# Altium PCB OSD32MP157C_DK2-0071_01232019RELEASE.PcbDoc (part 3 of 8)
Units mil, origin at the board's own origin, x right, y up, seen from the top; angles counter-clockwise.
Board outline 3976.38 x 2795.28 mil, 6 copper layers (Top Layer, Signal Layer 1, Signal Layer 2, Signal Layer 3, Signal Layer 4, Bottom Layer), stack 61.268 mil thick; 404 components, 418 nets, 1720 pads, 1233 vias.
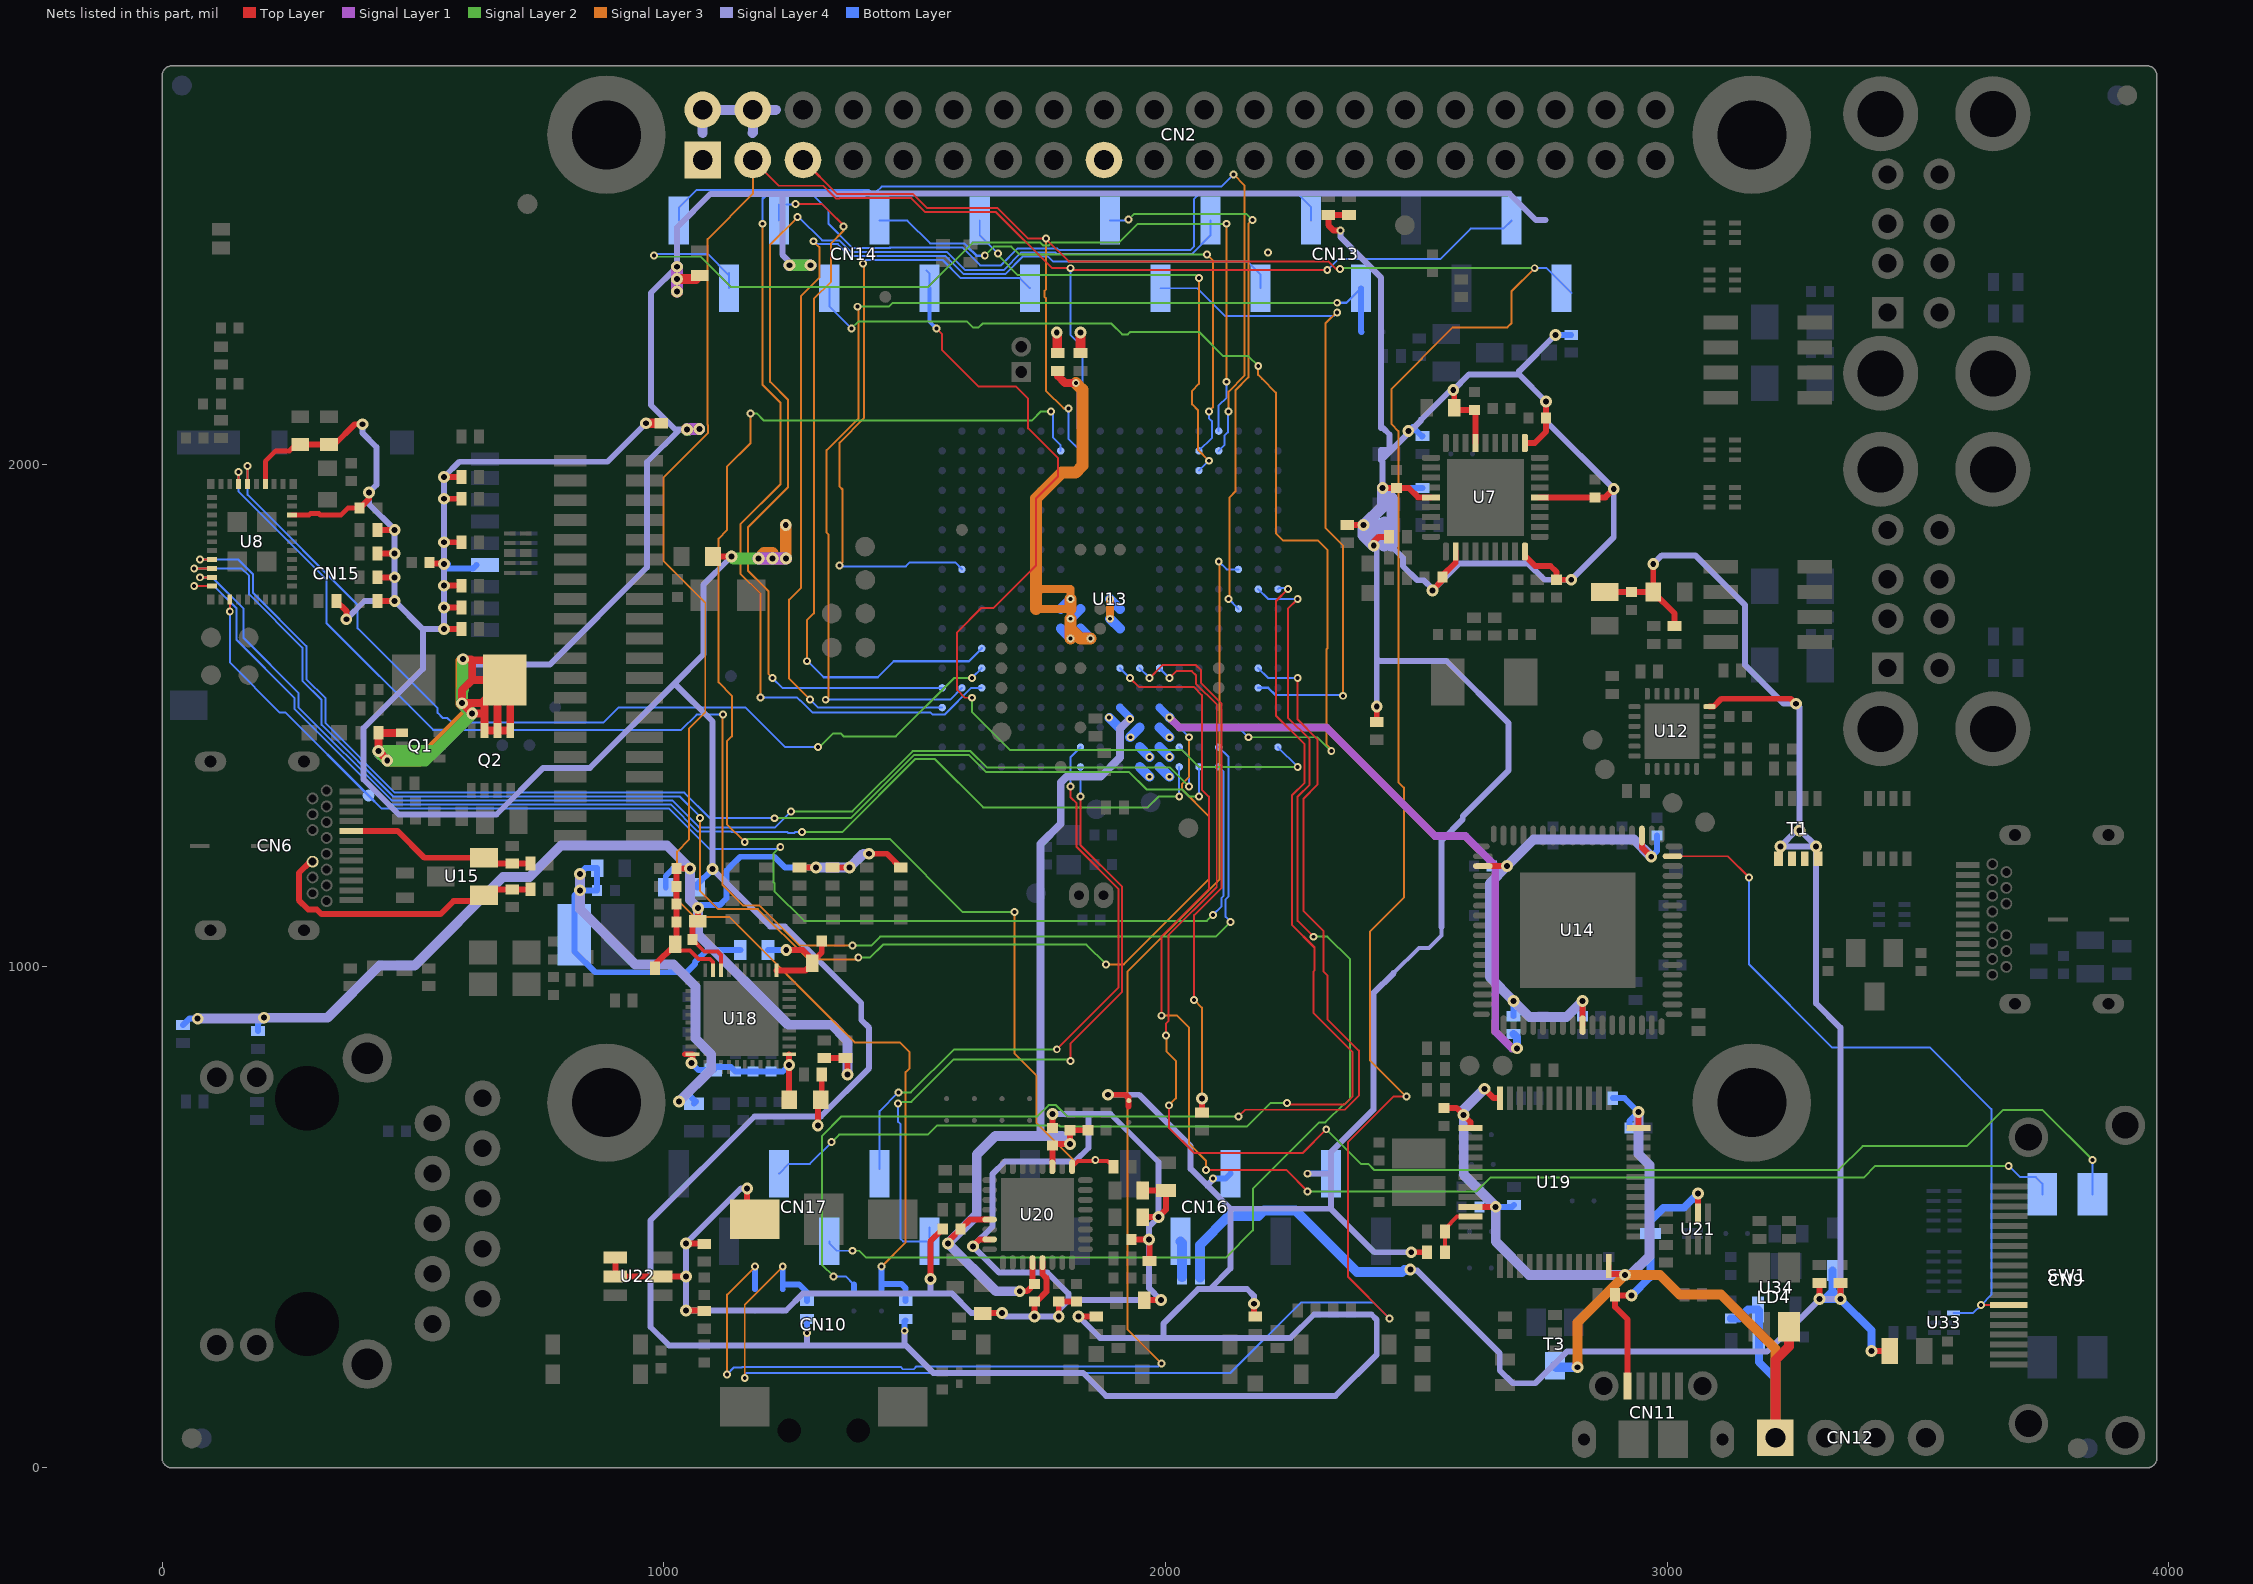
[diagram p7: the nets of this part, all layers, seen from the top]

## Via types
v1: diameter 15.75, hole 7.87, Top Layer to Bottom Layer, tented both sides, 803 vias
v2: diameter 23.62, hole 11.81, Top Layer to Bottom Layer, tented both sides, 417 vias
v3: diameter 15.75, hole 7.87, Top Layer to Bottom Layer, 13 vias

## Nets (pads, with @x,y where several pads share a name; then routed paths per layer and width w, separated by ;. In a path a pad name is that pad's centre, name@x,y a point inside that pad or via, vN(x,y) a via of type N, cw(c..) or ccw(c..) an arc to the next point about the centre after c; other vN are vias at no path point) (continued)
1V05_DVDD_GMII: C81.2 C85.2 R151.1 U18.21 | length 230.8
  Top Layer w11.81: U18.21@1224.41,992.13 1282.48,992.13 C85.2@1296.26,1005.91 C85.2@1296.26,1008.86 ; v2(1244.09,1032.48) 1277.56,1032.48 1296.26,1013.78 C85.2@1296.26,1008.86 ; C81.2@1314.96,1050.2 1314.96,1027.56 C85.2@1296.26,1008.86
  Bottom Layer w11.81: R151.1@1207.68,1032.48 v2(1244.09,1032.48)
1V05_GMII: C151.2 C157.2 LE1.2 R151.2 R160.2 | length 1332.6
  Signal Layer 4 w19.68: v2(832.68,1184.06) v2(832.68,1151.57) 832.68,1113.98 943.11,1003.54 1019.69,1003.54 1063.19,960.04 1063.19,855.91 1094.68,824.41 1094.68,794.54 v2(1030.44,730.31)
  Bottom Layer w11.81: v2(1030.44,730.31) 1047.21,747.08 1063.98,730.31 R160.2@1060.04,726.38 ; R151.2@1152.56,1032.48 1086.61,1032.48 1062.01,1007.87 1062.01,1004.47 1045.72,988.19 863.19,988.19 821.85,1029.53 LE1.2@821.85,1062.99 821.85,1140.75 v2(832.68,1151.57) ; v2(832.68,1151.57) C157.2@867.13,1151.57 C151.2@867.13,1195.87 843.5,1195.87 832.68,1185.04 v2(832.68,1184.06) v2(832.68,1151.57)
1V8_AUDIO: C94.2 C95.2 C97.2 C102.2 C107.2 U13.J4 U20.5 U20.12 U20.27 | length 1897.6
  Top Layer w3.54: v1(1929.13,1493.11) v1@1929.13,1494.59
  Top Layer w11.81: v2(1566.93,447.83) 1570.87,447.83 1570.87,455.71 C102.2@1591.54,476.38 1610.24,495.08 U20.5@1649.61,495.08 ; v2(1709.65,352.36) 1724.41,352.36 C107.2@1739.17,367.13 1735.24,371.06 U20.12@1735.24,409.45 ; U20.27@1774.61,600.39 C97.2@1774.61,642.72 1777.56,645.67 v2(1810.04,645.67) C94.2@1810.04,673.23 C95.2@1845.47,673.23
  Signal Layer 4 w15.75: 1749.02,662.01 1750.98,663.98 1750.98,1244.06 1791.34,1284.41 1791.34,1366.42 1802.87,1377.95 1870.97,1377.95 1909.45,1416.43 1909.45,1473.43 v1(1929.13,1493.11)
  Signal Layer 4 w19.68: v2(1709.65,352.36) 1662.4,352.36 v2(1566.93,447.83) 1624.02,504.92 1624.02,625.11 1660.91,662.01 1749.02,662.01 1793.7,662.01 v2(1810.04,645.67)
  Bottom Layer w3.54: U13.J4@1909.45,1514.27 U13.J4@1909.45,1515.75 ; v1(1929.13,1493.11) v1@1929.13,1494.59
  Bottom Layer w15.75: U13.J4@1909.45,1515.75 v1@1929.13,1496.06
3V3: C21.2 C23.2 C28.2 C29.2 C30.2 C38.2 C40.2 C45.2 C49.1 C50.2 C54.2 CN2.1 CN2.17 CN15.4 CN16.2 CN16.4 L7.1 L10.2 L11.2 R1.1 R2.1 R11.1 R14.2 R16.2 R17.1 R18.2 R19.2 R20.1 R22.1 R25.2 R26.1 R27.1 R28.2 R33.2 R40.1 R94.1 R105.2 R106.2 R114.2 R127.2 R134.2 R140.2 R166.1 R167.1 R300.1 R600.1 SB5.1 U7.5 U7.10 U7.15 U7.23 U7.29 U7.36 U8.30 U8.36 U13.H3 U13.J3 | length 15432.7
  Top Layer w9.84: U8.36@205.71,1961.61 205.71,2006.59 226.67,2027.56 253.94,2027.56 266.73,2040.35 C28.2@275.59,2040.35 ; U8.30@258.86,1899.61 292.62,1899.61 295.57,1902.56 312.7,1902.56 315.65,1899.61 356.3,1899.61 370.08,1913.39 C45.2@393.7,1913.39
  Top Layer w11.81: C28.2@275.59,2040.35 C29.2@332.68,2040.35 343.5,2040.35 383.85,2080.7 v2(399.61,2080.7) ; R26.1@347.45,1728.35 367.13,1708.67 v2(367.13,1691.93) ; C45.2@393.7,1913.39 412.4,1932.09 v2(412.4,1944.88) ; R27.1@429.14,1728.35 v2(463.59,1728.35) ; R22.1@429.14,1775.59 v2(463.59,1775.59) ; R20.1@429.14,1822.83 v2(463.59,1822.83) ; R17.1@429.14,1870.08 v2(463.59,1870.08) ; C49.1@533.07,1804.77 534.37,1803.47 560.71,1803.47 v2(562.01,1802.17) ; v2(562.01,1672.24) R33.2@596.46,1672.24 ; v2(562.01,1715.55) R28.2@596.46,1715.55 ; v2(562.01,1758.86) R25.2@596.46,1758.86 ; v2(562.01,1845.47) R19.2@596.46,1845.47 ; v2(562.01,1932.09) R16.2@596.46,1932.09 ; v2(562.01,1975.39) R14.2@596.46,1975.39 ; L7.1@1098.43,1816.93 v2(1134.84,1816.93) ; v2(1307.09,683.07) 1307.09,728.35 L10.2@1312.99,734.25 ; L10.2@1312.99,744.09 1314.96,746.06 R300.1@1314.96,784.45 ; v2(1826.77,302.17) R105.2@1862.2,302.17 ; v2(1885.83,744.09) 1920.28,744.09 1926.18,738.19 1926.18,720.47 ; v2(2176.38,327.36) 2176.38,304.92 R106.2@2179.13,302.17 ; v1(2349.41,2466.73) 2335.63,2466.73 2324.8,2477.56 R1.1@2324.8,2498.03 R2.1@2366.14,2498.03 ; R600.1@2362.45,1879.92 v2(2394.68,1879.92) ; v2(2415.35,1838.58) 2415.35,1846.46 2425.2,1856.3 R18.2@2445.87,1856.3 ; R40.1@2421.26,1487.2 v2(2421.26,1517.72) ; v2(2433.19,1953.84) 2460.53,1953.84 C38.2@2460.63,1953.74 2485.24,1953.74 2503.94,1935.04 U7.23@2529.53,1935.04 ; v2(2490.16,430.12) R94.1@2521.65,430.12 ; v2(2532.48,1749.02) 2532.48,1750 2552.17,1769.69 C50.2@2552.17,1776.57 2552.17,1778.54 2578.74,1805.12 U7.29@2578.74,1826.77 ; v2(2573.82,2148.62) 2575.79,2146.65 C23.2@2575.79,2113.19 2579.72,2109.25 C21.2@2616.14,2109.25 2618.11,2107.28 U7.15@2618.11,2043.31 ; U7.36@2716.54,1826.77 2716.54,1818.9 2737.2,1798.23 2767.72,1798.23 2779.53,1786.42 C54.2@2779.53,1770.67 v2(2809.06,1770.67) ; U7.10@2716.54,2043.31 2736.22,2043.31 2758.86,2065.94 C30.2@2758.86,2093.5 v2(2758.86,2125.98) ; U7.5@2746.06,1935.04 C40.2@2856.3,1935.04 2876.97,1935.04 v2(2893.7,1951.77)
  Top Layer w19.68: v2(964.57,2082.68) R11.1@995.08,2082.68
  Signal Layer 1 w23.62: v2(1188.98,1812.99) 1189.07,1813.08 v2(1243.99,1813.08)
  Signal Layer 2 w23.62: v2(1134.84,1816.93) 1138.69,1813.08 v2(1243.99,1813.08)
  Signal Layer 3 w23.62: v2(1243.11,1879.92) 1243.11,1813.97 v2(1243.99,1813.08) 1243.9,1812.99 v2(1216.54,1812.99) ; v2(1216.54,1812.99) 1216.54,1823.82 1199.8,1823.82 v2(1188.98,1812.99) v2(1216.54,1812.99)
  Signal Layer 4 w7.87: 2454.92,986.44 2505.48,1037.01 2525.59,1037.01 2550.39,1061.81 2550.39,1078.35
  Signal Layer 4 w11.81: v2(367.13,1691.93) 403.54,1728.35 v2(463.59,1728.35) ; v2(399.61,2080.7) 399.61,2062.99 427.17,2035.43 427.17,1959.65 v2(412.4,1944.88) 412.4,1921.27 v2(463.59,1870.08) v2(463.59,1822.83) v2(463.59,1775.59) v2(463.59,1728.35) ; v2(964.57,2082.68) 887.8,2005.91 592.52,2005.91 v2(562.01,1975.39) v2(562.01,1932.09) v2(562.01,1845.47) v2(562.01,1802.17) v2(562.01,1758.86) v2(562.01,1715.55) v2(562.01,1672.24) 519.69,1672.24 ; v2(1134.84,1816.93) v2@1131,1813.08 ; v2(1243.99,1813.08) v2@1131,1813.08 ; v1(1285.43,268.7) 1285.43,244.09 ; v1(1480.31,273.62) 1480.31,246.46 1482.29,244.49 ; v2(1826.77,302.17) 1869.49,259.45 1967.72,259.45 1995.28,259.45 ; v2(1885.83,744.09) 1947.64,744.09 2050.39,641.34 2050.39,596.26 2084.15,562.5 ; v3(2094.49,576.77) 2094.49,574.8 2084.15,564.47 2084.15,562.5 ; v2(2176.38,327.36) 2176.38,343.31 2162.8,356.89 2088.98,356.89 ; v3(2283.46,586.61) 2329.92,586.61 ; v1(2349.41,2466.73) 2349.41,2453.74 2430.12,2373.03 2430.12,2072.83 2434.17,2072.83 2446.85,2060.15 2446.85,2033.46 2442.91,2029.53 2430.12,2029.53 2430.12,2008.86 ; v2(2421.26,1517.72) 2421.26,1613.78 ; v2(2433.19,1953.84) 2433.19,2005.79 2430.12,2008.86 ; 2454.92,986.44 2414.57,946.09 2414.57,714.17 2329.92,629.53 2329.92,586.61 ; v2(2490.16,430.12) 2416.54,430.12 2329.92,516.73 ; v2(2532.48,1749.02) v2@2532.48,1750 ; 2550.39,1078.35 2550.39,1250.59 2592.8,1293 2592.8,1299.35 2684.25,1390.8 2684.25,1484.84 2560.24,1608.86 2426.18,1608.86 2421.26,1613.78 ; v2(2777.56,2258.86) 2705.12,2186.42 2705.12,2179.72 ; v2(463.59,1728.35) 519.69,1672.24 ; 519.69,1672.24 519.69,1592.92 401.57,1474.8 401.57,1372.83 471.65,1302.76 666.54,1302.76 759.45,1395.67 852.95,1395.67 1020.87,1563.58 ; 1020.87,1563.58 1021.85,1563.58 1097.44,1487.99 v2(1097.44,1193.9) 1212.01,1079.33 1241.34,1079.33 1393.7,926.97 1393.7,893.17 1409.45,877.42 1409.45,797.13 1313.1,700.79 1307.09,700.79 1180.71,700.79 973.62,493.7 973.62,281.1 1010.63,244.09 1285.43,244.09 ; 1020.87,1563.58 1078.94,1621.65 1078.94,1761.02 v2@1131,1813.08 ; 1285.43,244.09 1482.29,244.09 1482.29,244.49 ; 1482.29,244.49 1537.21,189.57 1835.83,189.57 1881.69,143.7 2339.17,143.7 2421.26,225.79 2421.26,295.72 2410.88,306.1 2296.15,306.1 2249.5,259.45 1995.28,259.45 ; 1995.28,259.45 1995.96,260.14 1995.96,287.7 2065.16,356.89 2088.98,356.89 ; 2084.15,562.5 2129.92,516.73 ; 2088.98,356.89 2129.92,397.83 2129.92,516.73 ; 2129.92,516.73 2329.92,516.73 ; 2329.92,516.73 2329.92,586.61 ; 2421.26,1613.78 2421.26,1832.68 v2(2415.35,1838.58) 2436.02,1838.58 2449.61,1838.58 2473.62,1814.57 2473.62,1797.83 2501.78,1769.68 2515.21,1769.68 2532.48,1752.41 v2@2532.48,1750 ; 2430.12,2008.86 2484.25,2062.99 v2(2484.25,2066.92) 2484.25,2070.85 2488.18,2066.92 2509.84,2088.58 2509.84,2090.02 2568.45,2148.62 v2(2573.82,2148.62) 2604.92,2179.72 2705.12,2179.72 ; v2@2532.48,1750 2585.23,1802.76 2723.62,1802.76 2755.71,1770.67 v2(2809.06,1770.67) 2893.7,1855.31 v2(2893.7,1951.77) 2893.59,1951.77 2758.86,2086.5 v2(2758.86,2125.98) 2705.12,2179.72
  Signal Layer 4 w23.62: v2@2395.67,1877.95 2411.42,1862.2 2412.4,1862.2 ; v2(2415.35,1838.58) 2394.68,1859.25 v2(2394.68,1879.92) v2@2395.67,1878.94 ; v2(2433.19,1953.84) v2@2433.19,1950.67 ; 2436.02,1838.58 2412.4,1862.2 ; 2449.61,1838.58 2452.76,1841.73 2452.76,1931.1 v2@2433.19,1950.67 ; v2@2395.67,1878.94 2433.19,1916.46 v2@2433.19,1950.67 ; v2@2395.67,1878.94 2412.4,1862.2 ; v2@2395.67,1878.94 2431.1,1878.94 2437.01,1884.84 2437.01,1862.2 2412.4,1862.2
  Bottom Layer w11.81: v2(562.01,1802.17) v2@569.88,1802.17 ; v2@565.45,1797.74 561.02,1793.31 620.08,1793.31 CN15.4@626.97,1800.2 ; L11.2@1066.93,1157.48 1066.93,1163.39 v2(1097.44,1193.9) ; v1(1285.43,268.7) R167.1@1285.43,297.24 ; v1(1480.31,273.62) 1480.31,292.52 R166.1@1482.29,294.49 ; v1(1887.8,1496.06) v1@1888.55,1495.31 ; v3(2094.49,576.77) 2119.9,576.77 CN16.4@2129.92,586.79 ; v3(2283.46,586.61) 2283.64,586.79 CN16.2@2329.92,586.79 ; v2(2394.68,1879.92) R140.2@2423.23,1879.92 ; v2(2433.19,1953.84) 2430.21,1953.84 2430.12,1953.74 R134.2@2512.8,1953.74 ; v2(2484.25,2066.92) 2484.25,2067.9 2485.23,2066.92 2493.11,2074.8 2511.81,2056.1 R127.2@2512.8,2057.09 ; v2(2777.56,2258.86) R114.2@2809.06,2258.86
  Bottom Layer w19.68: v1@1888.55,1495.31 1907.48,1476.38 U13.J3@1909.45,1476.38 ; v1@1929.13,1456.69 U13.H3@1948.82,1476.38
  Bottom Layer w23.62: v2(1188.98,1812.99) v2(1216.54,1812.99) 1243.9,1812.99 v2(1243.99,1813.08)
  other v1: 1930.13,1456.69
3V3_AVDD_GMII: C173.2 C174.2 C175.2 C176.2 L10.1 U18.11 U18.40 | length 326.2
  Top Layer w11.81: 1042.32,824.8 U18.40@1057.09,824.8 1057.09,809.04 v2(1055.17,807.13) ; L10.1@1250,744.09 v2(1250,803.15) U18.11@1250,824.8
  Bottom Layer w11.81: v2(1055.17,807.13) 1068.99,793.31 C173.2@1098.43,793.31 1098.72,793.01 1104.92,799.21 1133.86,799.21 C176.2@1142.72,790.35 C175.2@1178.15,790.35 C174.2@1213.58,790.35 1237.2,790.35 v2(1250,803.15)
3V3_DVDD_GMII: C74.2 C75.2 C76.1 C77.2 C78.2 C79.2 C80.2 L11.1 R52.2 R53.2 R55.2 R65.2 R75.2 R76.2 R156.1 R157.2 U18.28 U18.29 | length 3058.1
  Top Layer w7.87: C80.2@1022.64,1044.29 1022.64,1043.31 1022.64,1034.45 1025.59,1031.5 1052.17,1031.5 1068.9,1014.76 1092.52,1014.76 1098.43,1008.86 U18.29@1098.43,992.13 ; C79.2@1055.12,1051.18 C79.2@1057.09,1053.15 1080.71,1029.53 1107.28,1029.53 1114.17,1022.64 U18.28@1114.17,992.13
  Top Layer w11.81: R65.2@982.28,996.06 982.28,1002.95 C80.2@1022.64,1043.31 ; C80.2@1022.64,1044.29 1025.59,1047.24 C78.2@1025.59,1088.58 C77.2@1025.59,1124.02 C75.2@1025.59,1159.45 C74.2@1025.59,1194.88 v2(1052.17,1194.88) ; C79.2@1057.09,1053.15 1057.09,1078.74 C76.1@1067.91,1089.57 1067.91,1116.13 v2(1067.97,1116.19) ; R52.2@1270.67,1196.85 v2(1303.15,1196.85) ; R75.2@1319.88,816.93 R76.2@1362.2,816.93 1361.42,816.14 1366.14,811.42 v2(1366.14,784.45) ; R53.2@1337.6,1196.85 v2(1370.08,1196.85) ; v2(1409.45,1224.41) 1444.88,1224.41 R55.2@1472.44,1196.85
  Signal Layer 4 w19.68: v2(70.87,895.67) 200.79,895.67 v2(202.76,897.64) 329.33,897.64 433.27,1001.57 503.54,1001.57 679.72,1177.76 732.48,1177.76 795.47,1240.75 1006.3,1240.75 v2(1052.17,1194.88) 1052.17,1131.99 v2(1067.97,1116.19) 1067.97,1063.72 1248.23,883.46 1335.04,883.46 1350.39,868.11 1350.39,867.01 1363.08,854.33 1364.17,854.33 1366.14,852.36 v2(1366.14,784.45) ; v2(1303.15,1196.85) v2(1370.08,1196.85) 1397.64,1224.41 v2(1409.45,1224.41)
  Bottom Layer w11.81: R156.1@41.34,882.87 54.13,895.67 v2(70.87,895.67) ; R157.2@190.94,871.06 190.94,885.83 v2(202.76,897.64) ; L11.1@1003.94,1157.48 1003.94,1180.12 1018.7,1194.88 v2(1052.17,1194.88) ; v2(1067.97,1116.19) 1074.31,1122.54 1074.8,1122.05 1111.33,1122.05 1125,1135.72 1125,1190.83 1133.86,1199.69 1133.86,1200.2 1152.17,1218.5 1220.47,1218.5 1242.13,1196.85 v2(1303.15,1196.85)
3V3_HDMI: R154.2 U13.G4 | length 1218.8
  Signal Layer 1 w15.75: v1(2007.87,1496.06) 2027.56,1476.38 2320.87,1476.38 2537.78,1259.46 2598.43,1259.46 2657.48,1200.41 2657.48,870.08 2690.94,836.61 v2(2700.79,836.61)
  Bottom Layer w15.75: U13.G4@1988.19,1515.75 v1(2007.87,1496.06) ; R154.2@2693.9,865.16 2700.79,858.27 v2(2700.79,836.61)
3V3_IOVCC: C140.2 C154.2 C171.2 R154.1 U14.3 U14.21 U14.46 | length 1075.2
  Top Layer w11.81: U14.21@2632.87,1199.8 v2(2681.1,1199.8) ; U14.46@2831.69,882.87 v2(2831.69,931.1) ; U14.3@2949.8,1260.83 2949.8,1237.2 v2(2968.5,1218.5)
  Signal Layer 4 w19.68: v2(2831.69,931.1) 2799.8,899.21 2725.79,899.21 v2(2693.9,931.1) 2646.85,978.15 2646.85,1165.55 v2(2681.1,1199.8) 2733.86,1252.56 2934.45,1252.56 v2(2968.5,1218.5)
  Bottom Layer w11.81: C154.2@2650.59,1199.8 v2(2681.1,1199.8) ; R154.1@2693.9,900.59 v2(2693.9,931.1) ; C171.2@2831.69,900.59 v2(2831.69,931.1) ; v2(2968.5,1218.5) 2980.31,1230.31 C140.2@2980.31,1260.83
3V3_ST_LINK: C93.2 C181.2 C184.2 C186.2 C188.2 C190.2 CN12.1 LD4.4 R158.2 R161.2 T3.3 U19.1 U19.9 U19.24 U19.36 U19.48 U34.5 | length 2827.8
  Top Layer w11.81: C93.2@2555.12,717.52 2580.51,717.52 v2(2594.39,703.64) 2608.27,689.76 U19.1@2608.27,678.15 ; U19.9@2608.27,520.67 v2(2658.46,520.67) ; v2(2635.83,755.91) 2654.53,737.2 U19.48@2667.32,737.2 ; U19.24@2883.86,402.56 2883.86,386.81 2914.37,386.81 v2(2916.34,384.84) ; U19.36@2942.91,678.15 v2(2942.91,709.65)
  Top Layer w19.68: CN12.1@3216.14,60.04 3216.14,215.16 3243.11,242.13 LD4.4@3243.11,281.5
  Signal Layer 3 w19.68: v2(2821.85,200.79) 2821.85,290.35 v2(2916.34,384.84) 2986.02,384.84 3024.8,346.06 3107.48,346.06 3216.14,237.4 CN12.1@3216.14,60.04
  Signal Layer 4 w19.68: v2(2594.39,703.64) 2594.39,714.47 v2@2594.68,714.76 ; v2(2635.83,755.91) v2@2594.68,714.76 ; v2(2942.91,709.65) 2942.91,625.79 2964.76,603.94 2964.76,422.83 2926.77,384.84 v2(2916.34,384.84) 2725,384.84 2658.46,451.38 v2(2658.46,520.67) 2594.68,584.45 v2@2594.68,714.76
  Bottom Layer w11.81: C184.2@2625.98,520.67 v2(2658.46,520.67) 2690.94,520.67 R161.2@2694.88,524.61 ; C186.2@2883.86,384.84 v2(2916.34,384.84) ; R158.2@2891.73,737.2 2915.35,737.2 v2(2942.91,709.65) 2925.2,691.93 C181.2@2925.2,678.15
  Bottom Layer w15.75: C188.2@3126.97,298.23 3143.7,298.23 3161.42,315.94 U34.5@3181.1,315.94 3183.07,313.98 C190.2@3183.07,251.97 3183.07,211.22 3216.14,178.15 CN12.1@3216.14,60.04
  Bottom Layer w19.68: T3.3@2776.57,203.74 2779.53,200.79 v2(2821.85,200.79)
5V: CN16.5 R165.2 | length 73.3
  Bottom Layer w11.81: R165.2@2033.07,380.31 R165.2@2033.46,379.92
  Bottom Layer w19.68: CN16.5@2029.92,451.79 2033.07,448.64 R165.2@2033.07,380.31
5V_USB_ST_LINK: CN11.1 D2.1 R99.1 U21.5 | length 547.2
  Top Layer w11.81: CN11.1@2921.26,163.39 2921.26,296.26 2896.65,320.87 R99.1@2896.65,345.47 2898.62,343.5 v2(2929.13,343.5) ; U21.5@3062.01,508.07 v2(3062.01,547.24)
  Bottom Layer w15.75: v2(2929.13,343.5) 2966.73,381.1 D2.1@2966.73,467.52 2966.73,492.32 2993.11,518.7 3033.46,518.7 v2(3062.01,547.24)
5V_VIN: C55.2 C56.2 C60.1 CN2.2 CN2.4 D1.1 F1.1 L8.1 Q1.4 Q2.1 Q2.2 Q2.3 R9.1 R12.2 R32.2 R41.2 R97.2 R98.2 R165.1 T1.5 T1.6 T1.7 T1.8 U12.24 U13.G1 U13.G2 U13.G3 U13.H1 U13.H2 U23.1 | length 10501.4
  Top Layer w11.81: C55.2@2875.98,1746.06 C56.2@2929.13,1746.06 L8.1@2972.44,1746.06 ; v2(2972.44,1802.17) L8.1@2972.44,1746.06 ; R32.2@3014.76,1678.15 3014.76,1703.74 L8.1@2972.44,1746.06 ; U12.24@3084.65,1517.72 3092.52,1517.72 3108.27,1533.46 3246.85,1533.46 v2(3256.89,1523.43) ; v2(3304.13,336.61) R97.2@3304.13,369.09 ; v2(3345.47,336.61) R98.2@3345.47,369.09 ; v2(3407.48,233.27) F1.1@3441.93,233.27 ; F1.1@3443.9,235.24 F1.1@3441.93,233.27 ; F1.1@3444.88,234.25 F1.1@3443.9,233.27 F1.1@3441.93,233.27
  Top Layer w15.75: v2(448.82,1410.43) 448.82,1411.42 v2(431.1,1429.13) R41.2@431.1,1465.55 Q1.4@478.35,1465.55 ; v2(599.44,1612.28) 615.08,1612.28 ; v2(618.11,1503.94) 642.72,1503.94 ; v2@618.14,1503.97 v2(597.44,1524.61) ; 618.14,1570.84 597.44,1550.14 v2(597.44,1524.61) v2(597.44,1524.61) ; v2(1783.46,2263.78) v2@1784.45,2262.8 ; R12.2@1784.45,2223.43 R12.2@1785.43,2222.44 ; v2(597.44,1524.61) 636.81,1524.61 C60.1@642.72,1530.51 ; 615.08,1612.28 616.06,1612.28 618.11,1610.24 ; 615.08,1612.28 617.13,1610.24 618.11,1610.24 ; 618.11,1610.24 683.07,1610.24 C60.1@683.07,1570.87 ; 618.11,1610.24 618.11,1570.87 C60.1@683.07,1570.87 ; 642.72,1503.94 C60.1@642.72,1530.51 ; 642.72,1503.94 Q2.3@642.72,1470.47 Q2.2@668.31,1470.47 ; C60.1@642.72,1530.51 C60.1@668.31,1556.1 ; Q2.2@668.31,1470.47 Q2.1@693.9,1470.47 693.9,1560.04 C60.1@683.07,1570.87 ; Q2.2@668.31,1470.47 C60.1@668.31,1556.1 ; C60.1@668.31,1556.1 C60.1@683.07,1570.87
  Top Layer w19.68: v2(1026.57,2370.08) 1064.57,2370.08 U23.1@1071.85,2377.36 ; R12.2@1784.45,2223.43 v2@1784.45,2262.8 ; R9.1@1830.71,2222.44 v2(1830.71,2263.78)
  Signal Layer 1 w23.62: v2(1026.57,2345.47) v2(1026.57,2370.08) v2(1026.57,2394.69) ; v2@1047.24,2070.87 v2(1070.87,2070.87)
  Signal Layer 2 w11.81: v2(1046.26,2069.98) 1047.29,2069.98 1053.35,2069.98 1054.24,2070.87 v2@1055.17,2071.8
  Signal Layer 2 w23.62: v2(599.44,1612.28) 599.44,1552.14 597.44,1550.14 v2(597.44,1524.61) v2(597.44,1524.61) v2@618.14,1503.97 ; v2(618.11,1503.94) 543.31,1429.13 ; v2(1026.57,2345.47) v2(1026.57,2370.08) v2(1026.57,2394.69) ; v2(1046.26,2069.98) 1047.34,2068.9 1047.31,2069.66 1047.29,2069.98 1047.29,2070.04 1047.24,2070.87 1054.24,2070.87 v2(1070.87,2070.87) ; v2(1250.98,2397.64) v2(1292.32,2397.64) ; 543.31,1429.13 v2(431.1,1429.13) 431.1,1428.15 v2(448.82,1410.43) 524.61,1410.43 543.31,1429.13
  Signal Layer 3 w23.62: v2(599.44,1612.28) 596.46,1609.3 596.46,1523.62 v2(597.44,1524.61) v2(597.44,1524.61) v2@618.14,1503.97 ; v2(618.11,1503.94) 607.28,1503.94 532.48,1429.13 ; v2(1026.57,2345.47) v2(1026.57,2370.08) v2(1026.57,2394.69) ; v2(1046.26,2069.98) 1047.34,2068.9 1047.31,2069.66 1047.29,2070.04 1047.24,2070.87 v2(1070.87,2070.87) ; 532.48,1429.13 v2(431.1,1429.13) 431.1,1428.15 v2(448.82,1410.43) 513.78,1410.43 532.48,1429.13
  Signal Layer 4 w11.81: v2(597.44,1524.61) v2(597.44,1524.61) v2@599.44,1522.61 ; v2(599.44,1612.28) 610.34,1601.38 772.64,1601.38 966.73,1795.47 966.73,2005.51 1031.2,2069.98 ; v2@618.11,1501.97 v2(618.11,1503.94) ; v2@1055.17,2069.98 v2(1046.26,2069.98) 1031.2,2069.98 ; 1236.42,2536.02 1236.42,2418.9 1257.68,2397.64 v2(1292.32,2397.64) v2@1289.37,2394.69 ; v2(2488.19,395.67) 2490.45,393.41 2502.06,393.41 2666.54,228.94 2666.54,194.49 2692.13,168.9 2737.4,168.9 2800.39,231.89 3199.41,231.89 v2(3304.13,336.61) v2(3345.47,336.61) 3345.47,877.76 3297.24,925.98 v2(3297.24,1239.17) ; 2757.87,2487.8 2738.58,2487.8 2686.02,2540.35 1400.65,2540.35 1400.05,2539.76 1092.91,2539.76 1026.57,2473.43 v2(1026.57,2394.69) 974.61,2342.72 974.61,2118.7 1023.32,2069.98 1031.2,2069.98 ; v2(2972.44,1802.17) 2989.67,1819.4 3056.39,1819.4 3155.71,1720.08 3155.71,1600.2 3232.48,1523.43 v2(3256.89,1523.43) 3263.78,1516.54 v2(3263.78,1270.67) ; v2(3263.78,1270.67) 3257.87,1270.67 v2(3226.38,1239.17) v2(3297.24,1239.17) ; v2(3263.78,1270.67) 3265.75,1270.67 v2(3297.24,1239.17)
  Signal Layer 4 w19.68: v2(431.1,1429.13) 440.95,1419.29 535.43,1419.29 v2@618.11,1501.97 ; v2(597.44,1524.61) v2@599.44,1522.67 ; v2@599.44,1522.61 v2@599.44,1522.67 ; v2(599.44,1612.28) v2@599.44,1522.67 ; v2@618.14,1503.97 v2@599.44,1522.67 ; 1077.76,2661.61 1077.56,2661.81 CN2.2@1077.56,2707.48 CN2.4@1177.56,2707.48 ; 1177.17,2661.61 1177.56,2662.01 CN2.4@1177.56,2707.48 ; 1223.43,2707.68 1223.23,2707.48 CN2.4@1177.56,2707.48
  Bottom Layer w15.75: v2(3304.13,336.61) v2@3313.98,336.61 ; D1.1@3329.72,393.9 3329.72,352.36 ; v2(3407.48,233.27) 3407.48,274.61 v2(3345.47,336.61) ; v2@3313.98,336.61 v2(3345.47,336.61) ; v2@3313.98,336.61 3329.72,352.36 ; 3329.72,352.36 v2(3345.47,336.61)
  Bottom Layer w19.68: U13.H1@1948.82,1397.64 v1(1968.5,1377.95) ; U13.H2@1948.82,1437.01 v1(1968.5,1417.32) ; U13.G1@1988.19,1397.64 v1(2007.87,1377.95) ; U13.G2@1988.19,1437.01 v1(2007.87,1417.32) ; U13.G3@1988.19,1476.38 v1(2007.87,1456.69) ; R165.1@2068.9,379.92 2068.9,444.88 2125.98,501.97 2185.26,501.97 2196.36,513.07 2259.12,513.07 2381.68,390.51 2471.87,390.51 2476.28,394.92 2487.44,394.92 v2(2488.19,395.67)
  Bottom Layer w23.62: v2(431.1,1429.13) 431.1,1428.15 v2(448.82,1410.43) ; v2(597.44,1524.61) v2(597.44,1524.61) v2@618.14,1503.97 ; v2(1026.57,2345.47) v2(1026.57,2370.08) v2(1026.57,2394.69) ; v2(1046.26,2069.98) 1047.34,2068.9 1047.31,2069.66 1047.29,2070.04 1047.24,2070.87 v2(1070.87,2070.87) ; v2(1250.98,2397.64) v2(1292.32,2397.64)
  other v1: 2204.72,2423.23
AGND: C97.1 C100.1 C101.1 C102.1 C103.1 C107.1 C108.1 C109.1 C110.1 C111.1 CN10.2 R83.1 R92.1 R96.1 R103.1 U20.7 U20.13 U22.2 U22.4 U22.5 | length 3532.5
  Top Layer w11.81: U22.4@903.54,419.29 U22.5@903.54,381.89 U22.2@994.09,381.89 v2(1044.29,381.89) ; v2(1044.29,313.98) 1079.72,313.98 R103.1@1080.71,312.99 ; v2(1044.29,447.83) 1079.72,447.83 R92.1@1080.71,446.85 ; v2(1166.34,557.09) 1166.34,510.83 CN10.2@1181.1,496.06 ; v2(1531.5,376.57) 1531.5,451.77 C102.1@1556.1,476.38 ; v2(1616.14,441.93) 1629.92,455.71 U20.7@1649.61,455.71 ; C110.1@1635.83,308.07 1636.81,309.06 v2(1674.21,309.06) ; v2(1739.17,302.17) C107.1@1739.17,331.69 1743.11,331.69 1762.8,351.38 1762.8,378.49 1754.92,386.36 U20.13@1754.92,409.45 ; C97.1@1774.61,678.15 v2(1774.61,705.71) ; v2(1787.4,302.17) C108.1@1787.4,331.69 C109.1@1822.83,331.69 ; C103.1@1932.09,455.71 v2(1967.52,455.71) 1968.5,454.72 R96.1@1968.5,412.4 ; C101.1@1954.72,500 1987.2,500 v2(1986.22,500) 2000.98,514.76 R83.1@2000.98,553.15 C100.1@1954.72,553.15 ; C111.1@1957.68,334.65 v2(1991.14,334.65)
  Signal Layer 4 w11.81: v2(1166.34,557.09) 1153.54,557.09 v2(1044.29,447.83) v2(1044.29,381.89) v2(1044.29,313.98) 1243.7,313.98 1277.76,348.03 1531.69,348.03 ; v2(1531.5,376.57) 1531.69,376.38 1531.69,348.03 ; v2(1774.61,705.71) 1847.64,705.71 ; 1531.69,348.03 1574.02,348.03 1612.99,309.06 v2(1674.21,309.06) 1681.1,302.17 v2(1739.17,302.17) v2(1787.4,302.17) 1787.4,315.35 1806.69,334.65 ; 1806.69,334.65 1806.69,347.64 1764.96,389.37 1668.7,389.37 v2(1616.14,441.93) 1655.71,481.5 1655.71,586.22 1680.31,610.83 1819.49,610.83 1846.65,637.99 1846.65,704.72 1847.64,705.71 ; 1806.69,334.65 v2(1991.14,334.65) 1967.52,358.27 v2(1967.52,455.71) 1967.52,481.3 v2(1986.22,500) 1986.22,610.04 1890.55,705.71 1847.64,705.71
AIN_1: R91.2 R94.2 U19.10 | length 107.6
  Top Layer w7.87: R94.2@2557.09,430.12 R91.2@2557.09,471.46 2557.09,476.38 2581.69,500.98 U19.10@2608.27,500.98
ARD_A0: CN17.1 U13.L1 | length 1405
  Top Layer w3.94: v1(1811.02,811.02) 1811.02,846.46 1913.78,949.21 1913.78,1158.32 1830.71,1241.39 v1(1830.71,1338.58)
  Signal Layer 2 w3.94: v1(1466.73,726.97) 1469.67,729.91 1493.69,729.91 1578.34,814.56 1807.49,814.56 v1(1811.02,811.02)
  Bottom Layer w3.94: v1(1466.73,726.97) 1466.73,690.75 1471.65,685.83 1471.65,489.76 1471.65,457.28 1477.15,451.79 CN17.1@1529.92,451.79 CN17.1@1529.92,478.94 ; v1(1830.71,1338.58) U13.L1@1830.71,1397.64
ARD_A1: CN17.2 U13.L2 | length 1220.3
  Top Layer w3.94: v1(1783.46,834.65) 1906.3,957.48 1906.3,1154.5 1822.83,1237.96 1822.83,1324.8 1811.02,1336.61 v1(1811.02,1358.27)
  Signal Layer 2 w3.94: v1(1467.7,748.61) 1492.72,748.62 1578.74,834.65 v1(1783.46,834.65)
  Bottom Layer w3.94: CN17.2@1430.31,596.06 1430.31,711.22 v1(1467.7,748.61) ; v1(1811.02,1358.27) 1811.02,1417.32 U13.L2@1830.71,1437.01
ARD_A2: CN17.3 U13.B10 | length 2412.8
  Top Layer w3.94: v1(2263.78,1732.28) 2244.09,1712.6 2244.09,1495.67 2287.4,1452.36 2287.4,1362.2 2263.78,1338.58 2263.78,1090.55 v1(2295.28,1059.06)
  Signal Layer 2 w3.94: v1(1375.98,433.07) 1389.76,433.07 1403.54,419.29 2120.08,419.29 2174.41,473.62 2174.41,556.3 2307.09,688.98 2318.9,688.98 2355.31,725.39 2357.73,725.39 2368.11,735.77 2368.11,1013.78 2322.83,1059.06 v1(2295.28,1059.06)
  Bottom Layer w3.94: CN17.3@1330.33,451.38 CN17.3@1329.92,451.79 1329.92,447.64 1344.49,433.07 v1(1375.98,433.07) ; U13.B10@2185.04,1751.97 2204.72,1732.28 v1(2263.78,1732.28)
ARD_A3: CN17.4 U13.A10 | length 2338.6
  Top Layer w3.94: v1(2242.32,727.95) 2245.32,724.95 2357.29,724.95 2373.03,740.69 2373.03,828.74 2295.28,906.5 2295.28,990.16 2297.24,992.13 2297.24,1037.6 2251.97,1082.88 2251.97,1340.55 2277.56,1366.14 2277.56,1442.72 2220.47,1499.8 2220.47,1728.35 v1(2244.09,1751.97)
  Signal Layer 2 w3.94: v1(1334.65,649.61) 1349.41,664.37 1526.57,664.37 1545.28,683.07 1788.08,683.07 1790.05,681.1 2162.83,681.1 2209.68,727.95 v1(2242.32,727.95)
  Bottom Layer w3.94: CN17.4@1229.92,586.79 1249.43,606.3 1291.34,606.3 v1(1334.65,649.61) ; U13.A10@2224.41,1751.97 2226.58,1754.13 v1@2244.09,1754.13
ARD_A4: SB24.1 U13.B6 | length 2461.7
  Top Layer w3.94: v1(2145.67,700.79) 2159.04,714.16 2357.63,714.16 2385.83,742.35 2385.83,831.89 2322.83,894.88 2322.83,982.09 2314.96,989.96 2314.96,1070.87 2275.59,1110.24 2275.59,1334.65 2303.15,1362.2 2303.15,1452.76 2263.78,1492.13 v1(2263.78,1574.8)
  Signal Layer 2 w3.94: v1(1338.58,381.89) 1314.96,405.51 1314.96,661.42 1354.33,700.79 1744.63,700.79 1767.27,723.43 1781.94,723.43 1804.58,700.79 v1(2145.67,700.79)
  Bottom Layer w3.94: v1(1338.58,381.89) 1362.8,381.89 1378.94,365.75 ; U13.B6@2185.04,1594.49 2204.72,1574.8 v1(2263.78,1574.8)
  Bottom Layer w11.81: SB24.1@1378.94,356.3 1378.94,365.75
ARD_A5: SB26.1 U13.C11 | length 2912
  Signal Layer 3 w3.94: v1(1126.18,186.61) 1126.18,345.67 v1(1182.09,401.57) ; v1(1992.13,208.66) 1924.21,276.57 1924.21,989.67 2108.26,1173.72 2108.26,1745.47 2108.27,1805.12 v1(2106.3,1807.09)
  Bottom Layer w3.94: v1(1126.18,186.61) 1139.96,200.39 1155.91,200.39 1156.89,201.38 1472.05,201.38 1476.58,196.85 1497.91,196.85 1503.82,202.76 1576.01,202.76 1576.41,202.36 1985.83,202.36 v1(1992.13,208.66) ; v1(2106.3,1807.09) 2122.05,1791.34 U13.C11@2145.67,1791.34
  Bottom Layer w11.81: SB26.1@1182.09,356.3 v1(1182.09,401.57)
ARD_D0: CN14.1 U13.D17 | length 1743.6
  Signal Layer 3 w3.94: v1(2125.98,2106.3) 2125.98,2145.87 2157.48,2177.36 2157.48,2557.08 v1(2135.82,2578.73)
  Bottom Layer w3.94: CN14.1@1029.92,2486.79 1029.92,2512.6 1065.39,2548.07 1408.82,2548.07 1412.6,2544.29 1424.01,2544.29 1434.25,2554.53 2111.61,2554.53 v1(2135.82,2578.73) ; U13.D17@2106.3,2027.56 2118.11,2039.37 2118.11,2058.29 2124.51,2064.69 2124.51,2104.82 v1(2125.98,2106.3)
ARD_D1: CN14.2 U13.D18 | length 1875.5
  Signal Layer 2 w3.94: v1(980.31,2417.32) 983.07,2414.57 1073.62,2414.57 1133.86,2354.33 1527.56,2354.33 1615.75,2442.52 1750.59,2442.52 1756.1,2437.01 1767.52,2437.01 1773.03,2442.52 1907.09,2442.52 1944.88,2480.31 v1(2122.05,2480.31)
  Signal Layer 3 w3.94: v1(2122.05,2165.35) 2122.11,2165.41 2122.05,2165.47 v1(2122.05,2480.31)
  Bottom Layer w3.94: v1(980.31,2417.32) 977.36,2420.28 1087.6,2420.28 1129.92,2377.95 CN14.2@1129.92,2351.79 CN14.2@1129.92,2382.28 ; U13.D18@2106.3,2066.93 2106.3,2118.11 2122.05,2133.86 v1(2122.05,2165.35)
ARD_D2: CN14.3 U13.T7 | length 1463.7
  Top Layer w3.94: v1(1262.99,2519.86) 1315.37,2519.86 1327.95,2507.28 1359.35,2475.89 v1(1358.27,2474.8)
  Signal Layer 3 w3.94: v1(1285.43,1608.27) 1285.43,1689.85 1299.21,1703.63 1299.21,2330.47 1333.66,2364.92 1333.66,2441.4 1358.27,2466.01 v1(1358.27,2474.8)
  Bottom Layer w3.94: CN14.3@1229.92,2486.79 1229.92,2518.7 1261.83,2518.7 v1(1262.99,2519.86)
  Bottom Layer w4.72: v1(1285.43,1608.27) 1287.04,1608.27 1318.93,1576.38 1426.65,1576.38 1458.54,1608.27 1608.27,1608.27 U13.T7@1633.86,1633.86
ARD_D3: CN14.4 U13.C3 | length 2037.3
  Signal Layer 2 w3.94: v1(1374.02,2271.65) 1387.8,2285.43 1604.53,2285.43 1616.34,2273.62 1627.76,2273.62 1635.63,2281.5 1891.93,2281.5 1913.58,2259.84 1925,2259.84 1929.72,2264.57 2067.37,2264.57 2115.41,2216.53 2165.36,2216.53 v1(2185.04,2196.85) ; v1(2165.35,1456.69) 2303.15,1456.69 v1(2330.71,1429.13)
  Signal Layer 3 w3.94: v1(2185.04,2196.85) 2185.04,2179.13 2192.91,2171.26 2220.27,2143.9 2220.27,1863.44 2234.89,1848.82 2304.53,1848.82 2322.83,1830.51 2322.83,1633.66 2320.87,1631.69 2320.87,1442.91 2330.71,1433.07 v1(2330.71,1429.13)
  Bottom Layer w3.94: CN14.4@1329.92,2351.79 1329.92,2315.75 v1(1374.02,2271.65) ; U13.C3@2145.67,1476.38 v1(2165.35,1456.69)
ARD_D4: CN14.5 U13.E17 | length 1108.7
  Signal Layer 2 w3.94: v1(1639.96,2416.93) 1657.68,2434.65 1692.91,2434.65 1708.27,2419.29 v1(2082.68,2419.29)
  Signal Layer 3 w3.94: v1(2082.68,2419.29) 2094.49,2407.48 2094.49,2114.17 2090.89,2110.57 v1(2086.61,2106.3)
  Bottom Layer w3.94: CN14.5@1429.92,2486.79 1485.65,2486.79 1531.18,2441.26 1598.75,2441.26 1604.61,2435.4 ; U13.E17@2066.93,2027.56 2093.01,2053.64 2093.01,2086.12 2086.61,2092.52 v1(2086.61,2106.3)
  Bottom Layer w5.12: 1604.61,2435.4 1623.08,2416.93 v1(1639.96,2416.93)
ARD_D5: CN14.6 U13.A2 | length 1900.3
  Top Layer w3.94: v1(1543.31,2271.65) 1555.12,2259.84 1555.12,2228.35 1627.95,2155.51 1702.56,2155.51 1726.38,2131.69 1726.38,2072.64 1785.43,2013.58 1785.43,1976.32 1742.13,1933.01 1742.13,1799.21 1657.48,1714.57 1633.35,1714.57 1584.65,1665.86 1584.65,1551.18 1600.39,1535.43 v1(1614.17,1535.43)
  Signal Layer 2 w3.94: v1(1614.17,1535.43) 1614.17,1507.87 1690.94,1431.1 2033.46,1431.1 2066.93,1397.64 v1(2263.78,1397.64)
  Bottom Layer w3.94: CN14.6@1523.47,2387.4 1529.92,2380.95 CN14.6@1529.92,2351.79 ; U13.A2@2224.41,1437.01 v1(2263.78,1397.64)
  Bottom Layer w7.87: CN14.6@1529.92,2351.79 1529.92,2285.04 v1(1543.31,2271.65)
ARD_D6: CN14.7 U13.E16 | length 915.3
  Signal Layer 2 w3.94: v1(1666.54,2420.87) 1666.54,2417.47 1706.05,2377.95 1816.74,2377.95 2061.02,2377.95 v1(2066.92,2372.04)
  Signal Layer 3 w3.94: v1(2066.92,2372.04) 2066.92,2352.36 2066.93,2161.22 2053.15,2147.44 2053.15,2120.28 2064.96,2108.47 2064.96,2029.53 v1(2086.61,2007.87)
  Bottom Layer w3.94: CN14.7@1629.92,2486.77 1629.92,2457.48 v1(1666.54,2420.87) ; U13.E16@2066.93,1988.19 v1(2086.61,2007.87)
ARD_D7: CN14.8 U13.U11 | length 1241.6
  Signal Layer 3 w3.94: v1(1350.39,1799.21) 1356.3,1805.12 1356.3,1950.59 1350.39,1956.49 1350.39,2044.04 1399.61,2093.26 1399.61,2398.59 v1(1396.85,2401.35)
  Bottom Layer w3.94: v1(1350.39,1799.21) 1352.37,1797.24 1482.48,1797.24 1490.36,1805.12 1580.71,1805.12 U13.U11@1594.49,1791.34 ; v1(1396.85,2401.35) 1403.57,2408.07 1556.3,2408.07 1592.32,2372.05 1709.69,2372.05 CN14.8@1729.92,2351.81
ARD_D8: CN13.1 U13.C9 | length 1100.9
  Signal Layer 2 w3.94: v1(1926.38,2488.78) 1937.6,2500 2161.42,2500 v1(2173.23,2488.19)
  Signal Layer 3 w3.94: v1(2125.98,1732.28) 2127.95,1734.25 2127.95,1935.04 2139.76,1946.85 2139.76,2148.51 2165.35,2174.1 2165.35,2480.31 v1(2173.23,2488.19)
  Bottom Layer w3.94: CN13.1@1889.92,2486.79 1924.39,2486.79 v1(1926.38,2488.78) ; v1@2129.92,1732.28 v1(2125.98,1732.28) U13.C9@2145.67,1712.6
ARD_D9: CN13.2 U13.B5 | length 1344
  Signal Layer 3 w3.94: v1@2342.52,2305.12 2318.9,2281.5 2318.9,1874.02 2354.33,1838.58 v1(2354.33,1539.37)
  Bottom Layer w3.94: CN13.2@1989.92,2351.79 2063.37,2351.79 2118.31,2296.85 2336.22,2296.85 v1(2342.51,2303.15)
  Bottom Layer w4.72: U13.B5@2185.04,1555.12 2205.06,1555.12 2219.23,1540.94 2352.76,1540.94 v1(2354.33,1539.37)
ARD_D10: CN13.3 U13.V5 | length 2284.1
  Signal Layer 3 w3.94: v1(1216.54,1574.8) 1208.46,1582.87 1208.46,1748.23 1167.91,1788.78 1167.91,1875.1 1247.64,1954.83 1247.64,2129.82 1212.2,2165.25 1212.2,2438.98 v1(1266.93,2493.7) ; v1@1266.63,2494 v1@1266.73,2494.09
  Bottom Layer w3.94: v1(1216.54,1574.8) 1236.22,1555.12 U13.V5@1555.12,1555.12 ; v1(1266.93,2493.7) 1269.46,2493.7 1315.75,2447.41 1350.25,2447.41 1373.85,2423.82 1565.13,2423.82 1601.15,2387.8 1677.45,2387.8 1712.88,2423.23 1780.62,2423.23 1783.97,2419.88 2052.36,2419.88 2089.92,2457.44 CN13.3@2089.92,2486.79
ARD_D11: CN13.4 U13.V4 | length 2206.4
  Signal Layer 3 w3.94: v1(1291.34,1532.09) 1250,1573.43 1250,1731.19 1273.62,1754.81 1273.62,2336.61 1310.04,2373.03 1310.04,2433.63 v1(1298.23,2445.44)
  Bottom Layer w3.94: v1(1291.34,1532.09) 1307.68,1515.75 U13.V4@1555.12,1515.75 ; v1(1298.23,2445.44) 1300.42,2445.44 1306.33,2439.54 1346.99,2439.54 1370.58,2415.94 1561.87,2415.94 1597.89,2379.92 1680.71,2379.92 1716.14,2415.35 1765.75,2415.35 1775.59,2405.51 2163.19,2405.51 2189.92,2378.78 CN13.4@2189.92,2351.79
ARD_D12: CN13.5 U13.T5 | length 2880.2
  Signal Layer 3 w3.94: v1@1188.98,1539.76 v1(1193.11,1535.63) 1193.11,1742.43 1152.56,1782.98 1152.56,1880.91 1232.68,1961.02 1232.68,2123.62 1196.85,2159.45 v1(1196.85,2480.31)
  Bottom Layer w3.94: v1(1193.11,1535.63) 1265.75,1535.63 1271.85,1529.53 1272.95,1529.53 1296.57,1505.91 1531.99,1505.91 1535.43,1502.46 1560.62,1502.46 1613.28,1555.12 U13.T5@1633.86,1555.12 ; v1(1196.85,2480.31) 1196.85,2531.5 1197.81,2530.53 1207.48,2540.2 1295.04,2540.2 1327.95,2507.28 ; 1330.71,2504.53 1327.95,2507.28 ; CN13.5@2289.92,2486.79 2289.92,2514.02 2262.01,2541.93 2069.21,2541.93 2057.28,2530.01 2057.28,2435.94 2049.1,2427.76 1787.23,2427.76 1783.88,2431.1 1706.03,2431.1 1672.24,2397.31 1630.72,2397.31 1594.65,2433.39 1449.83,2433.39 1451.52,2431.69 1377.11,2431.69 1327.95,2480.85 1327.95,2507.28
ARD_D13: CN13.6 SB6.1 U13.U5 | length 2202.6
  Signal Layer 2 w3.94: v1(1385.83,2314.96) 1448.82,2314.96 1456.69,2322.83 v1(2342.51,2322.83)
  Signal Layer 3 w3.94: v1(1322.83,1531.5) 1328.74,1537.4 1328.74,1860.43 1324.8,1864.37 1324.8,2029.03 1387.8,2092.02 1387.8,2312.99 v1(1385.83,2314.96)
  Bottom Layer w3.94: v1(1322.83,1531.5) 1570.87,1531.5 U13.U5@1594.49,1555.12
  Bottom Layer w4.72: v1(2342.51,2322.83) 2360.96,2322.83 CN13.6@2389.92,2351.79
  Bottom Layer w11.81: CN13.6@2389.92,2351.79 2389.92,2265.59 SB6.1@2390.75,2264.76
ARD_D14: CN2.3 CN13.9 R166.2 SB23.1 U13.L18 | length 4757.2
  Top Layer w3.94: CN2.3@1177.56,2607.48 1228.94,2556.1 1317.8,2556.1 1343.39,2530.51 1349.5,2530.51 1350.48,2531.5 1493.79,2531.5 1521.65,2503.63 1662.27,2503.63 1774.17,2391.73 v1(1811.03,2391.73) 1814.96,2387.8 v1(2322.66,2387.8)
  Signal Layer 3 w3.94: CN2.3@1177.56,2607.48 1177.56,2539.76 1087.6,2449.8 1087.6,2079.19 1088.58,2078.2 1088.58,2063.53 999.21,1974.16 999.21,1808.55 1082.68,1725.08 1082.68,1506.27 1050.2,1473.79 1050.2,1252.5 1026.57,1228.88 1026.57,1132.53 1060.63,1098.47 1130.55,1098.47 1358.26,870.76 1358.26,870.27 1366.34,862.2 1366.82,862.2 1380.6,848.43 1470.47,848.43 1490.16,828.74 1490.16,797.05 1482.28,789.17 1482.28,449.8 v1(1434.06,401.57) ; v1(2322.66,2387.8) v1@2322.83,2387.62
  Bottom Layer w3.94: v1(1811.03,2391.73) 1811.03,2258.4 1835.14,2234.3 1835.14,2157.19 1824.8,2146.85 1824.8,2072.83 U13.L18@1830.71,2066.93 ; v1(2322.66,2387.8) 2344.8,2409.93 2547.72,2409.93 2608.27,2470.47 2673.62,2470.47 CN13.9@2689.92,2486.77
  Bottom Layer w11.81: SB23.1@1434.06,356.3 1434.06,367.13 ; v1(1434.06,401.57) 1434.06,367.13 ; R166.2@1482.28,332.68 1482.28,358.27 1473.43,367.13 1434.06,367.13
ARD_D15: CN2.5 CN13.10 R167.2 SB25.1 U13.L17 | length 6291.8
  Top Layer w3.94: CN2.5@1277.56,2607.48 1345.67,2539.37 1497.05,2539.37 1524.92,2511.5 1665.66,2511.5 1726.38,2450.79 v1(1761.81,2450.79) 1807.09,2405.51 2324.43,2405.51 2340.18,2389.76 v1(2348.1,2389.76) ; v1(2447.08,297.8) 2364.17,380.71 2364.17,650.06 2454.28,740.16 v1(2480.31,740.16)
  Signal Layer 2 w3.94: v1(2348.1,2389.76) 2350.07,2391.73 2730.31,2391.73 2736.22,2397.64 v1(2736.22,2391.73)
  Signal Layer 3 w3.94: v1(1161.42,179.13) 1161.42,325.79 v1(1237.2,401.57) ; v1(1761.81,2450.79) 1761.81,2349.21 1758.86,2346.26 1758.86,2334.84 1761.81,2331.89 1761.81,2147.64 1797.24,2112.2 v1(1807.09,2112.2) ; v1(2480.31,740.16) 2407.48,812.99 2407.48,1068.9 2475.59,1137.01 2475.59,1356.1 2464.57,1367.13 2464.57,2066.93 2450.78,2080.71 2450.78,2151.37 2573.03,2273.62 2681.89,2273.62 2689.96,2281.69 2689.96,2345.47 v1(2736.22,2391.73)
  Bottom Layer w3.94: v1(1161.42,179.13) 1161.42,186.42 1164.37,189.37 2129.72,189.37 2270.67,330.31 2414.57,330.31 v1(2447.08,297.8) ; v1(1807.09,2112.2) 1807.09,2051.18 U13.L17@1830.71,2027.56 ; v1(2736.22,2391.73) 2759.84,2391.73 CN13.10@2809.61,2341.97
  Bottom Layer w11.81: SB25.1@1237.2,356.3 1237.2,366.14 ; v1(1237.2,401.57) 1237.2,366.14 ; R167.2@1285.43,332.68 1285.43,350.39 1269.68,366.14 1237.2,366.14
AUDIO_RST: R84.2 U13.M17 U20.25 | length 2891.5
  Top Layer w7.87: U20.25@1813.98,600.39 1825.79,612.2 1884.84,612.2 R84.2@1896.65,600.39
  Signal Layer 2 w3.94: v1(1161.42,1248.03) 1167.32,1253.94 1450.79,1253.94 1596.46,1108.27 v1(1698.82,1108.27) ; v1(1173.23,2102.36) 1185.04,2102.36 1198.82,2088.58 1734.25,2088.58 1751.97,2106.3 v1(1771.65,2106.3)
  Signal Layer 3 w3.94: v1(1161.42,1248.03) 1125.98,1283.46 1125.98,1448.82 1135.83,1458.66 1135.83,1539.37 1109.25,1565.94 1109.25,1852.67 1125.98,1869.4 1125.98,1996.06 1173.23,2043.31 v1(1173.23,2102.36) ; v1(1698.82,1108.27) 1698.82,826.57 1743.11,782.28 1743.11,687.54 1820.42,610.24 1856.3,610.24 v1(1860.24,614.17)
  Bottom Layer w3.94: v1(1771.65,2106.3) 1775.59,2102.36 1775.59,2054.44 1791.34,2038.69 U13.M17@1791.34,2027.56
BOOT0: SW1.1 U13.J6 | length 2974.7
  Top Layer w3.94: v1@1929.13,1574.8 1946.85,1557.09 2056.21,1557.09 2072.83,1540.47 2072.83,1352.16 2086.61,1338.38 2086.61,1153.54 1992.13,1059.06 v1(1992.13,901.57) ; v1(2080.91,594.09) 2240.55,594.09 v1(2283.46,551.18)
  Signal Layer 2 w3.94: v1(2283.46,551.18) 2620.08,551.18 2647.64,578.74 3391.73,578.74 3415.35,602.36 v1(3681.1,602.36)
  Signal Layer 3 w3.94: v1(1992.13,901.57) 2023.62,901.57 2047.24,877.95 2047.24,646.2 2080.91,612.54 v1(2080.91,594.09)
  Bottom Layer w3.94: U13.J6@1909.45,1594.49 v1@1929.13,1574.8 ; v1(3681.1,602.36) 3703.74,579.72 3735.24,579.72 3748.23,566.73 SW1.1@3748.23,545.28
  other v1: 1929.53,1574.8
BOOT1: R82.2 U13.H6 | length 1073.1
  Top Layer w3.94: v1(1968.5,1574.8) 1994.09,1600.39 2061.02,1600.39 2071.06,1590.35 2071.06,1564.51 2112.2,1523.37 2112.2,1156.86 2057.3,1101.96 v1(2057.3,933.07)
  Top Layer w11.81: R82.2@2072.83,708.66 v2(2072.83,736.22)
  Signal Layer 3 w3.94: v1(2057.3,933.07) 2072.83,917.53 v2(2072.83,736.22)
  Bottom Layer w3.94: U13.H6@1948.82,1594.49 v1(1968.5,1574.8)
BOOT2: SW1.2 U13.G6 | length 3140
  Top Layer w3.94: v1(2000.98,862.2) 2000.98,886.02 2005.91,890.95 2005.91,1061.7 2102.36,1158.16 2102.36,1522.07 2060.92,1563.51 2060.92,1569 2061.02,1569.1 2061.02,1580.51 2052.95,1588.58 2021.65,1588.58 v1(2007.87,1574.8) ; v1(2007.09,723.03) 2007.09,677.95 2057.09,627.95 2273.42,627.95 v1(2320.67,675.2)
  Signal Layer 2 w3.94: v1(2320.67,675.2) 2389.57,606.3 2403.99,606.3 2415.8,594.49 3342.52,594.49 3389.76,641.73 3597.44,641.73 3669.29,713.58 3748.62,713.58 v1(3848.23,613.98)
  Signal Layer 3 w3.94: v1(2000.98,862.2) 2002.17,861.02 2002.17,830.91 2001.97,830.71 2020.87,811.81 2020.87,736.81 v1(2007.09,723.03)
  Bottom Layer w3.94: U13.G6@1988.19,1594.49 v1(2007.87,1574.8) ; SW1.2@3848.23,545.28 v1(3848.23,613.98)
BST_IN: R12.1 U13.L8 U13.L9 U13.M8 U13.M9 | length 963.8
  Top Layer w15.75: R12.1@1787.4,2185.04 R12.1@1785.43,2187.01 1785.43,2177.17 1799.7,2162.89 v3(1821.36,2162.89)
  Signal Layer 3 w15.75: 1742.13,1712.6 1811.02,1712.6 v1(1811.02,1692.91) ; 1742.13,1742.13 1751.97,1751.97 1779.81,1751.97 1811.02,1751.97 v1(1811.02,1732.28)
  Signal Layer 3 w23.62: 1742.13,1712.6 1742.13,1923.23 1742.13,1933.01 1793.37,1984.25 1820.81,1984.25 1834.65,1998.09 1834.65,2149.61 v3(1821.36,2162.89) ; v1(1811.02,1653.54) 1811.02,1673.23 ; v1(1811.02,1692.91) 1811.02,1673.23 ; 1811.02,1712.6 v1(1811.02,1732.28) ; v1(1850.39,1653.54) 1830.71,1653.54 1811.02,1673.23
  Bottom Layer w19.68: U13.M8@1791.34,1673.23 v1(1811.02,1653.54) ; U13.M9@1791.34,1712.6 v1(1811.02,1732.28) ; v1(1811.02,1692.91) U13.L9@1830.71,1712.6 ; U13.L8@1830.71,1673.23 v1(1850.39,1653.54)
BST_OUT: U13.J8 U13.J9 | length 95
  Signal Layer 3 w15.75: v1(1889.76,1692.91) v1(1889.76,1732.28)
  Bottom Layer w19.68: v1(1889.76,1692.91) U13.J8@1909.45,1673.23 ; v1(1889.76,1732.28) U13.J9@1909.45,1712.6
BT_DEV_WAKE: U8.39 U13.D2 | length 3073.8
  Top Layer w3.94: U8.39@152.56,1961.61 v1(152.56,1985.23)
  Signal Layer 2 w3.94: v1(1375.98,1041.34) 1413.39,1041.34 1431.1,1059.06 2100.39,1059.06 v1(2129.92,1088.58)
  Signal Layer 3 w3.94: v1(1118.11,1501.97) 1117.32,1501.18 1117.32,1162.2 1157.87,1121.65 1190.55,1121.65 1270.87,1041.34 v1(1375.98,1041.34)
  Bottom Layer w3.94: v1(152.56,1985.23) 152.56,1946.44 327.37,1771.63 327.37,1684.44 540.35,1471.46 1034.78,1471.46 1065.3,1501.97 v1(1118.11,1501.97) ; U13.D2@2106.3,1437.01 2125.98,1417.32 2125.98,1139.37 2120.08,1133.46 2120.08,1098.43 v1(2129.92,1088.58)
BT_HOST_WAKE: U8.38 U13.T6 | length 1891.6
  Top Layer w3.94: U8.38@170.28,1961.61 v1(170.28,1997.07)
  Signal Layer 2 w3.94: v1(1307.09,1437.01) 1309.93,1437.01 1337.49,1464.57 1352.36,1464.57 1358.27,1458.66 1462.52,1458.66 1578.66,1574.8 v1(1614.17,1574.8)
  Bottom Layer w3.94: v1(170.28,1997.07) 170.28,1939.86 389.8,1720.34 389.8,1673.95 549.21,1514.54 549.21,1505.46 559.59,1495.08 568.67,1495.08 577.53,1486.22 879.92,1486.22 909.45,1515.75 1163.39,1515.75 1242.13,1437.01 v1(1307.09,1437.01) ; v1(1614.17,1574.8) U13.T6@1633.86,1594.49
BT_PCM_CLK: U8.11 U13.F1 | length 2421.8
  Top Layer w3.94: v1(63.95,1757.87) U8.11@99.41,1757.87
  Signal Layer 2 w3.94: v1(1275.59,1267.72) 1355.8,1267.72 1501.47,1413.39 1540.05,1413.39 1636.5,1316.93 1965,1316.93 1986.66,1338.58 v1(2027.56,1338.58)
  Bottom Layer w3.94: v1(63.95,1757.87) 104.14,1757.87 148.62,1713.39 148.62,1650.59 263.78,1535.43 263.78,1513.24 454.19,1322.83 1013.58,1322.83 1067.13,1269.29 1134.06,1269.29 1135.63,1267.72 1246.26,1267.72 1248.23,1265.75 1259.64,1265.75 1261.61,1267.72 v1(1275.59,1267.72) ; v1(2027.56,1338.58) U13.F1@2027.56,1397.64
BT_PCM_SDI: U8.10 U13.F2 | length 2431.6
  Top Layer w3.94: v1(75.8,1775.59) U8.10@99.41,1775.59
  Signal Layer 2 w3.94: v1(1253.94,1309.06) 1375.98,1309.06 1496.06,1429.13 1611.47,1429.13 1644.54,1396.06 2009.45,1396.06 v1(2047.24,1358.27)
  Bottom Layer w3.94: v1(75.8,1775.59) 99.41,1775.59 162.4,1712.6 162.4,1654.53 271.65,1545.28 271.65,1516.51 457.45,1330.71 1016.84,1330.71 1070.39,1277.17 1222.05,1277.17 v1(1253.94,1309.06) ; U13.F2@2027.56,1437.01 2047.24,1417.32 v1(2047.24,1358.27)
BT_PCM_SDO: U8.9 U13.F3 | length 2994.5
  Top Layer w3.94: v1(63.95,1793.31) U8.9@99.41,1793.31
  Signal Layer 2 w3.94: v1(1387.79,1017.71) 1411.42,1017.71 1437.01,1043.31 1842.52,1043.31 v1(1881.89,1003.94)
  Signal Layer 3 w3.94: v1(1071.85,1296.09) 1071.85,1151.13 1108.8,1114.17 1187.46,1114.17 1287.85,1013.78 1383.86,1013.78 v1(1387.79,1017.71) ; v1(1881.89,1003.94) 1917.32,1003.94 2086.61,1173.23 2086.61,1299.41 2033.46,1352.56 2033.46,1363.98 2047.24,1377.75 v1(2047.24,1456.69)
  Bottom Layer w3.94: v1(63.95,1793.31) 158.16,1793.31 173.23,1778.23 173.23,1741.6 279.53,1635.3 279.53,1569.35 317.91,1530.96 317.91,1516.26 ; 317.88,1516.23 317.88,1481.41 460.71,1338.58 1032.27,1338.58 1071.85,1299 v1(1071.85,1296.09) ; U13.F3@2027.56,1476.38 v1(2047.24,1456.69)
BT_PCM_WS: U8.8 U13.E1 | length 2463
  Top Layer w3.94: v1(75.8,1811.02) U8.8@99.41,1811.02
  Signal Layer 2 w3.94: v1(1220.47,1295.28) 1372.78,1295.28 1498.77,1421.26 1608.76,1421.26 1642.23,1387.79 1927.17,1387.79 1962.4,1352.56 2033.46,1352.56 2047.44,1338.58 v1(2066.93,1338.58)
  Bottom Layer w3.94: v1(75.8,1811.02) 151.57,1811.02 181.1,1781.5 181.1,1744.86 287.4,1638.56 287.4,1572.61 325.79,1534.22 325.79,1491.56 325.76,1484.67 463.97,1346.46 1040.97,1346.46 1092.15,1295.28 v1(1220.47,1295.28) ; v1(2066.93,1338.58) U13.E1@2066.93,1397.64
BT_REG_ON: TP29.1 U8.14 U13.D1 | length 2685
  Top Layer w3.94: v1(134.84,1707.69) U8.14@134.84,1731.3
  Signal Layer 2 w3.94: v1(1232.28,1238.19) 1218.5,1224.41 1218.5,1168.11 1220.47,1166.14 1220.47,1150.03 1279.95,1090.55 2082.68,1090.55 v1(2094.49,1102.36)
  Bottom Layer w3.94: v1(134.84,1707.69) 134.84,1605.85 234.79,1505.91 246.06,1505.91 TP29.1@411.42,1340.55 437.01,1314.96 1010.32,1314.96 1091.03,1234.25 1228.35,1234.25 v1(1232.28,1238.19) ; v1(2094.49,1102.36) 2112.2,1120.08 2112.2,1136.73 2116.14,1140.66 2116.14,1387.8 U13.D1@2106.3,1397.64
CC1: CN6.A5 R48.2 R49.1 U15.2 | length 384
  Top Layer w11.81: CN6.A5@377.17,1269.68 469.49,1269.68 522.64,1216.54 U15.2@641.73,1216.54 653.54,1204.72 R48.2@697.83,1204.72 R49.1@734.25,1204.72
CC2: CN6.B5 R56.1 R57.2 U15.1 | length 584.4
  Top Layer w11.81: CN6.B5@300,1208.66 295.31,1208.66 272.64,1185.99 272.64,1131.89 291.34,1113.19 295.28,1113.19 295.49,1113.4 308.28,1113.4 317.35,1104.33 555.12,1104.33 580.71,1129.92 629.92,1129.92 U15.1@641.73,1141.73 653.54,1153.54 R57.2@697.83,1153.54 R56.1@734.25,1153.54
CEC_A: CN9.13 U14.71 U33.1 | length 1462.1
  Top Layer w3.94: U14.71@3010.83,1219.49 3121.06,1219.49 v1(3163.39,1177.17) ; v1(3625.98,324.8) CN9.13@3681.1,324.8
  Bottom Layer w3.94: v1(3163.39,1177.17) 3163.39,1003.94 3328.74,838.58 3523.62,838.58 3646.65,715.55 3646.65,345.47 v1(3625.98,324.8) 3610.24,309.06 U33.1@3570.87,309.06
